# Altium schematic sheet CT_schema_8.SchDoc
size 278 x 170 mm
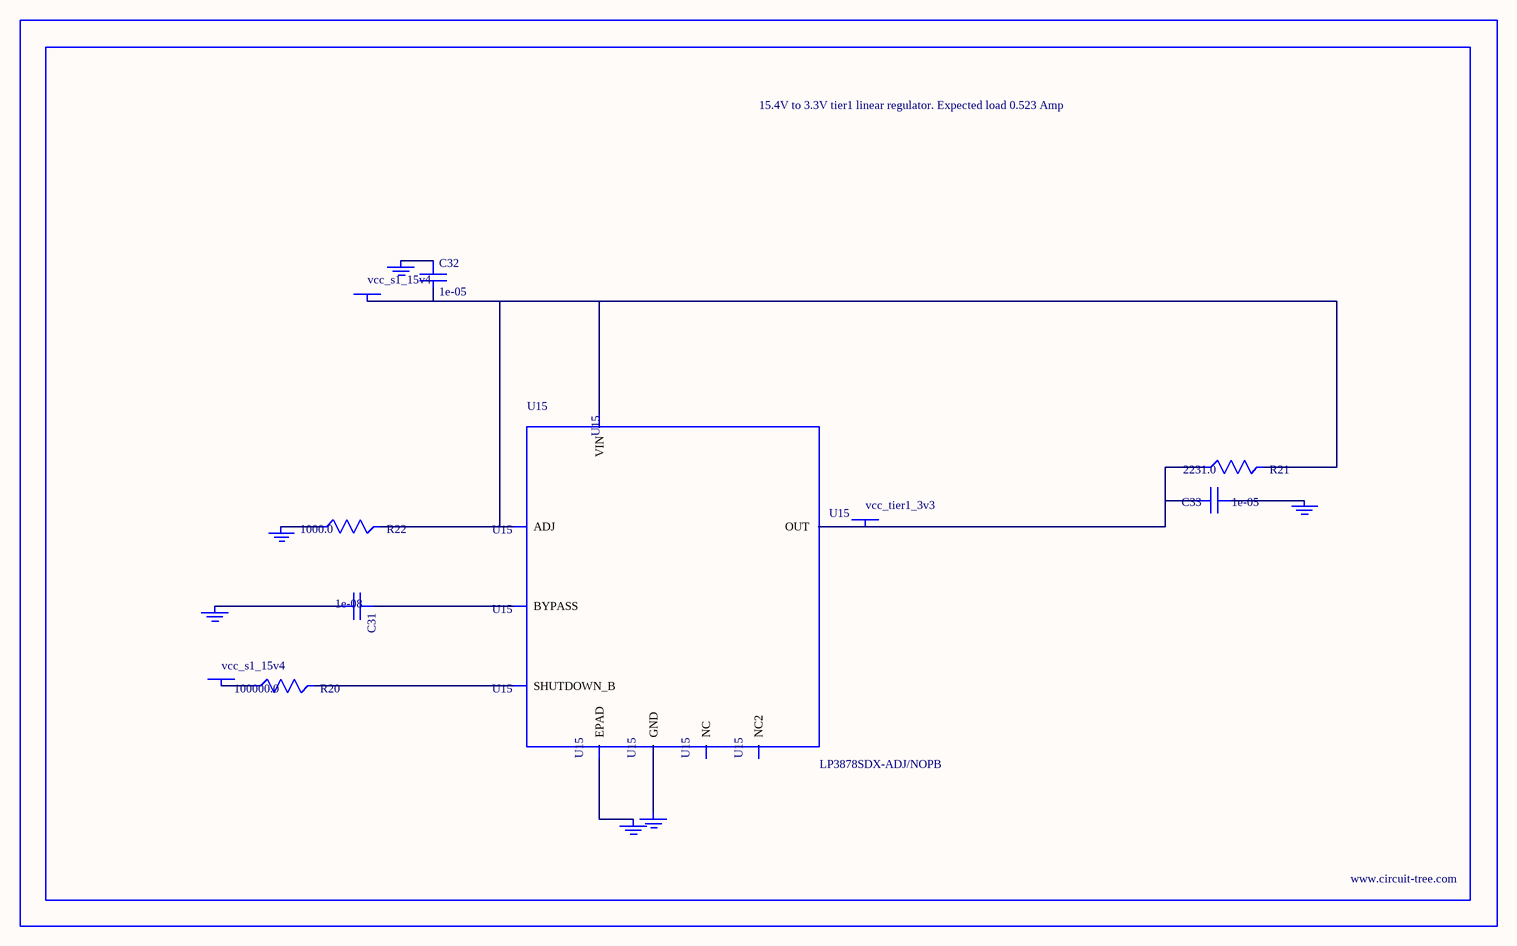
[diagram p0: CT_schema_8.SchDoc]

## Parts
BORDER7  (no value)
C31  1e-08  [C0402]
C32  1e-05  [C1210]
C33  1e-05  [C1210]
GND_INSTANCE_7_0  (no value)
GND_INSTANCE_7_1  (no value)
GND_INSTANCE_7_2  (no value)
GND_INSTANCE_7_3  (no value)
GND_INSTANCE_7_4  (no value)
GND_INSTANCE_7_5  (no value)
POWER_INSTANCE_7_0  vcc_s1_15v4
POWER_INSTANCE_7_1  vcc_s1_15v4
POWER_INSTANCE_7_2  vcc_tier1_3v3
R20  100000.0  [R0603]
R21  2231.0  [R0603]
R22  1000.0  [R0603]
U15  LP3878SDX-ADJ/NOPB  [WSON-8]

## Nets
NetC31_1: C31.1 U15.1(BYPASS)
NetC31_2: C31.2 GND_INSTANCE_7_0.0(GND)
NetC32_1: C32.1 GND_INSTANCE_7_1.0(GND)
NetC32_2: C32.2 POWER_INSTANCE_7_0.0(PWR) R21.2 R22.2 U15.4(VIN) U15.6(ADJ)
NetC33_1: C33.1 GND_INSTANCE_7_2.0(GND)
NetC33_2: C33.2 POWER_INSTANCE_7_2.0(PWR) R21.1 U15.5(OUT)
NetGND_INSTANCE_7_3_0: GND_INSTANCE_7_3.0(GND) R22.1
NetGND_INSTANCE_7_4_0: GND_INSTANCE_7_4.0(GND) U15.PAD(EPAD)
NetGND_INSTANCE_7_5_0: GND_INSTANCE_7_5.0(GND) U15.3(GND)
NetPOWER_INSTANCE_7_1_0: POWER_INSTANCE_7_1.0(PWR) R20.1
NetR20_2: R20.2 U15.8(SHUTDOWN_B)

Not connected (* = marked no-connect by the designer): U15 2(NC) 7(NC2)

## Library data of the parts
BORDER7 = BORDER_PAGE7
C31 = C0402C103K3RAC
C32 = C1210C106K5PACTU
C33 = GRM32DR61E106MA12L
GND_INSTANCE_7_0-GND_INSTANCE_7_5 = GND
POWER_INSTANCE_7_0-POWER_INSTANCE_7_2 = PWR
R20 = RC0603JR-07100KL
R21 = R21
R22 = RC0603JR-071KL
